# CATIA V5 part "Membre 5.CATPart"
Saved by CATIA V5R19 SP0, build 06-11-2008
Part number: Membre 5
Bounding box of the stored display mesh (mm): x -5 to 5, y -15 to 15, z -15 to 315
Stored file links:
  D:\thinkmotion-MPB\CIAO82010_JCF\PLANTECOSTE\0593\assemblage 593\Membre 5.CATPart
  D:\thinkmotion-MPB\CIAO82010_JCF\PLANTECOSTE\0593\assemblage 593\593-Plantecoste.CATProduct
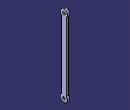
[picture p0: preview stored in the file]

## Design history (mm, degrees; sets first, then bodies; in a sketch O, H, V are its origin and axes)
External parameters (linked from other documents)
  `External.Diamètre axe` = 10 mm
  External.Longueur.1 = 300 mm
Body1 (main body)
  Sketch1 on yz-plane, origin (0, 0, 0), H (0, 1, 0), V (0, 0, 1)
    circle A1 centre (0, 0) radius 5
    axis line L1 (0, 0) -> (0, 133.3077)
    point P1 (0, 0)
    arc A2 centre (0, 0) radius 15 from (0, -15) to (10, 11.1803) ccw
    point P3 (0, -15)
    point P4 (10, 11.1803)
    line L2 (10, 11.1803) -> (10, 288.8197)
    point P5 (10, 288.8197)
    arc A3 centre (0, 300) radius 15 from (10, 288.8197) to (0, 315) ccw
    point P6 (0, 300)
    point P7 (0, 315)
    point P8 (10, 288.8197)
    circle A4 centre (0, 300) radius 5
    point P9 (-10, 11.1803)
    point P10 (0, -15)
    arc A5 centre (0, 0) radius 15 from (0, -15) to (-10, 11.1803) cw
    point P12 (-10, 288.8197)
    line L3 (-10, 11.1803) -> (-10, 288.8197)
    point P13 (0, 315)
    point P14 (-10, 288.8197)
    arc A6 centre (0, 300) radius 15 from (-10, 288.8197) to (0, 315) cw
    radius A1 = 5 {= `External.Diamètre axe` /2}
    radius A2 = 15 {= `External.Diamètre axe` *1.5}
    radius A4 = 5 {= `External.Diamètre axe` /2}
    radius A3 = 15 {= `External.Diamètre axe` *1.5}
    distance L2 L1 = 10 {= `External.Diamètre axe`}
    distance P6 H = 300 {= External.Longueur.1}
    coincidence: P1 H, P1 V, P3 V, P6 L1, P7 L1, P8 P5, P3 P10, P7 P13, P12 P14
    vertical: L1 V, L2 V
    symmetry: P4 P9 L1, P3 P10 L1, A2 A5 L1, P5 P12 L1, L2 L3 L1, P7 P13 L1, P8 P14 L1, A3 A6 L1
  Pad1: profile Sketch1, direction (1, 0, 0), length 5, opposite side length 5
